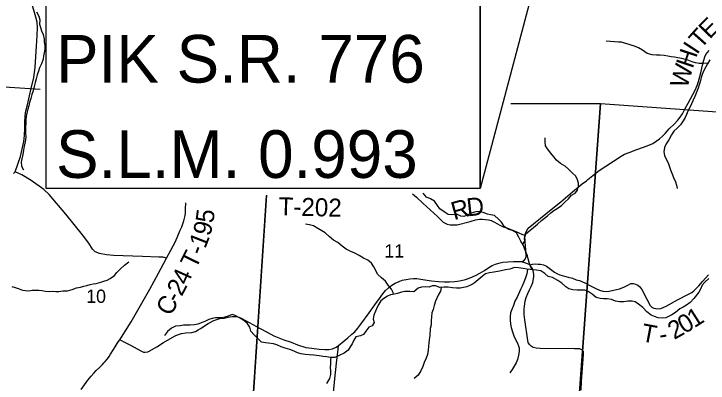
# Model space of a CAD drawing. Extents: x 0 to 40.8, y 0 to 22.
# Drawn here: x 5.517 to 7.699, y 15.059 to 16.222 of the extents above; entities that cross this region are included whole.
import ezdxf

# ---------------------------------------------------------------- set-up
doc = ezdxf.new("R2010")
doc.units = 0
for name, color, linetype in [('Default', 7, 'Continuous'), ('GM_X_County_Road', 7, 'Continuous'), ('GM_X_County_Road_Text', 7, 'Continuous'), ('GM_X_Minor_River', 7, 'Continuous'), ('GM_X_Section', 7, 'Continuous'), ('GM_X_Section_Text', 7, 'Continuous'), ('GM_X_Township_Road', 7, 'Continuous'), ('GM_X_Township_Road_Text', 7, 'Continuous')]:
    doc.layers.add(name, color=color, linetype=linetype)

msp = doc.modelspace()

# ---------------------------------------------------------------- linework, layer by layer
at = {"layer": 'Default'}
for points in [[(6.9829, 16.5037), (7.4797, 17.5479), (6.9829, 15.6724)], [(5.6188, 16.5037), (6.9829, 16.5037), (6.9829, 15.6724), (5.6188, 15.6724)]]:
    msp.add_lwpolyline(points, close=True, dxfattribs=at)
at = {"layer": 'GM_X_County_Road'}
for points in [[(5.5205, 15.725), (5.5376, 15.7735), (5.5479, 15.8205), (5.55, 15.8396), (5.5512, 15.8618), (5.551, 15.8837), (5.5538, 15.9116), (5.5595, 15.9361), (5.5656, 15.964), (5.5716, 15.9872), (5.5793, 16.0216), (5.5835, 16.0533), (5.5862, 16.0879), (5.5883, 16.1208), (5.5905, 16.1541), (5.5913, 16.1789), (5.5897, 16.1957), (5.5855, 16.2123), (5.5718, 16.2585)], [(7.3217, 15.7004), (7.3369, 15.7133), (7.3565, 15.7285), (7.3779, 15.7425), (7.4262, 15.7738), (7.4371, 15.7802), (7.4516, 15.786), (7.475, 15.7947), (7.4966, 15.802), (7.5132, 15.8086), (7.5256, 15.8142), (7.5358, 15.8211), (7.5467, 15.8292), (7.5559, 15.8374), (7.5646, 15.846), (7.5775, 15.8603), (7.5923, 15.875), (7.604, 15.8875), (7.6111, 15.8966), (7.6185, 15.9078), (7.6271, 15.9239), (7.6368, 15.9406), (7.6584, 15.9821), (7.6655, 15.9963), (7.6696, 16.0096), (7.6762, 16.0368), (7.6818, 16.0602), (7.6859, 16.0764), (7.6887, 16.0866), (7.6925, 16.0945), (7.7029, 16.1067)], [(5.5156, 15.7199), (5.5205, 15.725)], [(5.9972, 15.453), (5.9861, 15.4557), (5.9721, 15.4562), (5.9217, 15.4586), (5.83, 15.4613), (5.8081, 15.4634), (5.7861, 15.4673), (5.7729, 15.4727), (5.7643, 15.4815), (5.7523, 15.5005), (5.7331, 15.5261), (5.6798, 15.5916), (5.6283, 15.6533), (5.6112, 15.6694), (5.5708, 15.697), (5.5419, 15.7151), (5.5205, 15.725)], [(5.7287, 15.0393), (5.7498, 15.0691), (5.7597, 15.0811), (5.7681, 15.091), (5.7757, 15.0994), (5.7856, 15.1083), (5.7953, 15.1177), (5.7999, 15.1233), (5.804, 15.1279), (5.8111, 15.1365), (5.8162, 15.1434), (5.821, 15.151), (5.8299, 15.165), (5.835, 15.1734), (5.8413, 15.1838), (5.8462, 15.1907), (5.8497, 15.1955), (5.8548, 15.1935), (5.8627, 15.1899), (5.8815, 15.1802), (5.8953, 15.1726), (5.9161, 15.1607), (5.9245, 15.1574), (5.9301, 15.1571), (5.9375, 15.1584), (5.9423, 15.1604), (5.9665, 15.1741), (5.9876, 15.1871), (6.0145, 15.2031), (6.0242, 15.2085), (6.0318, 15.2118), (6.0443, 15.2159), (6.058, 15.2179), (6.0763, 15.2192), (6.088, 15.2225), (6.0967, 15.227), (6.1041, 15.2311), (6.1272, 15.2476), (6.146, 15.2565), (6.1648, 15.2629), (6.1781, 15.2639), (6.191, 15.2675), (6.203, 15.2693), (6.2093, 15.2693), (6.217, 15.269), (6.2246, 15.2672), (6.231, 15.2642), (6.2567, 15.2499), (6.291, 15.2311), (6.3129, 15.2197), (6.3342, 15.2085), (6.3658, 15.196), (6.3889, 15.1884), (6.409, 15.1805), (6.4349, 15.1721), (6.454, 15.1693), (6.4766, 15.1668), (6.495, 15.1655), (6.5074, 15.1655), (6.5184, 15.168), (6.5296, 15.1724), (6.5377, 15.178), (6.5554, 15.1922), (6.5673, 15.2018), (6.579, 15.2133), (6.5887, 15.2214), (6.5979, 15.2323), (6.6078, 15.2451), (6.634, 15.2809), (6.652, 15.3061), (6.666, 15.3262), (6.6764, 15.3404), (6.6853, 15.3516), (6.6942, 15.36), (6.7052, 15.3684), (6.7151, 15.3745), (6.7281, 15.3799), (6.738, 15.3832), (6.7499, 15.3862), (6.7616, 15.388), (6.7731, 15.3885), (6.784, 15.3885), (6.796, 15.3872), (6.8084, 15.3852), (6.8301, 15.3819), (6.8522, 15.3796), (6.8705, 15.3786), (6.8868, 15.3788), (6.9031, 15.3799), (6.912, 15.3809), (6.9229, 15.3824), (6.9369, 15.3862), (6.9519, 15.391), (6.9679, 15.3987), (6.9819, 15.4053), (6.9964, 15.4142), (7.0101, 15.4231), (7.0208, 15.4294), (7.031, 15.4343), (7.0417, 15.4376), (7.0544, 15.4399), (7.0701, 15.4414), (7.0879, 15.4427), (7.1115, 15.4421), (7.1201, 15.4447), (7.1247, 15.4496), (7.1275, 15.457), (7.1262, 15.4781), (7.1239, 15.5045), (7.1234, 15.5249), (7.1263, 15.534), (7.1337, 15.5472), (7.2062, 15.6063), (7.2362, 15.6306), (7.2726, 15.6614), (7.3031, 15.6873), (7.3171, 15.6965), (7.3217, 15.7004)], [(5.8497, 15.1955), (5.8857, 15.2529), (5.9441, 15.3555), (5.9718, 15.4058), (5.9972, 15.453)]]:
    msp.add_lwpolyline(points, dxfattribs=at)
at = {"layer": 'GM_X_Minor_River'}
for points in [[(5.5877, 16.2286), (5.5957, 16.2145), (5.5983, 16.2031), (5.5972, 16.1902), (5.6002, 16.1792), (5.6036, 16.169), (5.6093, 16.1576), (5.6116, 16.1428), (5.6123, 16.1333), (5.6139, 16.1227), (5.6139, 16.1113), (5.6116, 16.0996), (5.6097, 16.0897), (5.6089, 16.0795), (5.604, 16.0647), (5.5976, 16.0522), (5.5945, 16.0415), (5.5904, 16.0305), (5.5869, 16.0176), (5.5835, 16.0063), (5.5809, 15.993), (5.5775, 15.9797), (5.5737, 15.9687), (5.5699, 15.9562), (5.5665, 15.9433), (5.5642, 15.9331), (5.5612, 15.9224), (5.5578, 15.9099), (5.5555, 15.8989), (5.5543, 15.8894), (5.554, 15.8773), (5.5532, 15.8678), (5.5536, 15.8568), (5.5532, 15.8469), (5.554, 15.834), (5.5521, 15.8192), (5.5494, 15.8056), (5.5475, 15.7935), (5.5445, 15.779), (5.5422, 15.7661), (5.5403, 15.7555), (5.5411, 15.743), (5.5475, 15.7316)], [(7.6986, 16.0667), (7.6847, 16.0664), (7.6718, 16.066), (7.6597, 16.0675), (7.6491, 16.0709), (7.6385, 16.0755), (7.6279, 16.0789), (7.6169, 16.0816), (7.6044, 16.0842), (7.5942, 16.0861), (7.5836, 16.0873), (7.573, 16.0892), (7.5608, 16.0914), (7.5476, 16.0922), (7.537, 16.0926), (7.5233, 16.0937), (7.5078, 16.0979), (7.4934, 16.1081), (7.4805, 16.1157), (7.468, 16.1206), (7.4578, 16.1241), (7.4479, 16.1267), (7.437, 16.1301), (7.4275, 16.1328), (7.4176, 16.1328), (7.4048, 16.1339), (7.3911, 16.1351), (7.379, 16.1362)], [(7.7044, 16.077), (7.6976, 16.0649), (7.6923, 16.0554), (7.6851, 16.0417), (7.6805, 16.0311), (7.6775, 16.0216), (7.6749, 16.0083), (7.6718, 15.9989), (7.6684, 15.9882), (7.662, 15.9723), (7.6578, 15.9621), (7.6517, 15.9488), (7.6476, 15.9393), (7.6434, 15.9294), (7.6362, 15.9158), (7.6317, 15.9055), (7.6271, 15.8961), (7.6207, 15.8858), (7.6123, 15.8729), (7.6017, 15.8627), (7.5915, 15.8524), (7.5843, 15.8414), (7.5756, 15.8251), (7.5676, 15.8126), (7.5627, 15.8012), (7.56, 15.7879), (7.5619, 15.7762), (7.5668, 15.7663), (7.5737, 15.7534), (7.5771, 15.7436), (7.5816, 15.7314), (7.5858, 15.7204), (7.5907, 15.7071), (7.5968, 15.6931), (7.6002, 15.6832), (7.6024, 15.6719)], [(7.1165, 15.4974), (7.1237, 15.5068), (7.1226, 15.5163), (7.126, 15.5296), (7.1401, 15.5413), (7.1503, 15.5497), (7.1629, 15.5599), (7.1754, 15.5713), (7.1852, 15.5784), (7.1947, 15.586), (7.205, 15.5959), (7.2148, 15.6031), (7.2247, 15.6091), (7.2383, 15.6186), (7.2493, 15.6292), (7.2604, 15.6394), (7.2698, 15.6512), (7.2812, 15.6576), (7.2892, 15.6671), (7.2915, 15.6792), (7.2915, 15.6891), (7.2877, 15.7023), (7.2828, 15.7118), (7.2726, 15.7206), (7.2605, 15.7327), (7.2499, 15.7422), (7.2355, 15.7506), (7.2223, 15.7616), (7.2147, 15.7719), (7.2045, 15.7833), (7.1943, 15.797), (7.1887, 15.8065), (7.1868, 15.8205), (7.1876, 15.8315)], [(7.1466, 15.4167), (7.141, 15.4271), (7.1369, 15.4393), (7.1342, 15.4507), (7.132, 15.4602), (7.1263, 15.4731), (7.1226, 15.4829), (7.1195, 15.4924), (7.1112, 15.5061), (7.1041, 15.519), (7.0969, 15.5323), (7.0848, 15.5399), (7.073, 15.5433), (7.0598, 15.5521), (7.05, 15.5658), (7.0409, 15.5753), (7.0284, 15.5874), (7.0155, 15.5893), (7.0057, 15.592), (6.9921, 15.597), (6.9792, 15.5996), (6.9689, 15.5989), (6.9545, 15.5944), (6.942, 15.5879), (6.9314, 15.5842), (6.9216, 15.5857), (6.9095, 15.591), (6.8939, 15.5895), (6.8826, 15.5907), (6.8693, 15.5987), (6.8564, 15.6086), (6.8485, 15.6184), (6.8394, 15.6321), (6.8269, 15.6397), (6.8137, 15.6451), (6.8039, 15.6576)], [(6.7103, 15.3389), (6.709, 15.3451), (6.7037, 15.3554), (6.6939, 15.3683), (6.6848, 15.3808), (6.6723, 15.3907), (6.6602, 15.4021), (6.6549, 15.4143), (6.6485, 15.4257), (6.6413, 15.4367), (6.6292, 15.4462), (6.6164, 15.4534), (6.6024, 15.4618), (6.5884, 15.4682), (6.5762, 15.4736), (6.5615, 15.4816), (6.5486, 15.4911), (6.535, 15.5021), (6.5221, 15.5097), (6.5077, 15.5207), (6.4956, 15.5329), (6.4854, 15.5394), (6.4726, 15.5462), (6.4593, 15.5546), (6.4461, 15.558), (6.4339, 15.5603)], [(5.5107, 15.3636), (5.5205, 15.3606), (5.5338, 15.356), (5.5437, 15.3526), (5.5535, 15.3507), (5.5634, 15.3503), (5.5743, 15.3519), (5.5849, 15.3522), (5.5952, 15.3522), (5.6054, 15.3511), (5.6149, 15.3492), (5.6297, 15.3484), (5.6391, 15.3488), (5.6486, 15.348), (5.6584, 15.3484), (5.6713, 15.3496), (5.6857, 15.3503), (5.6997, 15.3545), (5.7134, 15.3594), (5.7266, 15.3613), (5.7373, 15.3643), (5.7467, 15.3666), (5.7562, 15.3697), (5.7657, 15.3719), (5.7751, 15.3734), (5.7899, 15.3772), (5.8001, 15.3807), (5.81, 15.3833), (5.8195, 15.3886), (5.8327, 15.3989), (5.8407, 15.4083), (5.8517, 15.4197), (5.8642, 15.4307), (5.8778, 15.441)], [(7.1035, 15.4223), (7.0906, 15.4238), (7.0762, 15.4185), (7.0622, 15.4159), (7.0486, 15.4136), (7.0387, 15.4114), (7.0254, 15.4087), (7.0122, 15.4072), (7.0001, 15.4038), (6.9887, 15.3951), (6.9769, 15.3845), (6.9644, 15.3743), (6.9542, 15.369), (6.9405, 15.3626), (6.9303, 15.3603), (6.9204, 15.3588), (6.9083, 15.3581), (6.8954, 15.3596), (6.8825, 15.3615), (6.8681, 15.3616), (6.856, 15.3608), (6.842, 15.3654), (6.8322, 15.3654), (6.8227, 15.3616), (6.8106, 15.3624), (6.7988, 15.3617), (6.7882, 15.3583), (6.7742, 15.3473), (6.7613, 15.3477), (6.7461, 15.3485), (6.7351, 15.3455), (6.723, 15.3413), (6.7135, 15.3394), (6.701, 15.3375), (6.6912, 15.3334), (6.6802, 15.3262), (6.6703, 15.3182), (6.6642, 15.3084), (6.6593, 15.2989), (6.654, 15.2864), (6.649, 15.2739), (6.646, 15.2614), (6.6497, 15.2507), (6.6433, 15.2401), (6.6323, 15.236), (6.6232, 15.2227), (6.6163, 15.2128), (6.6061, 15.2083), (6.5924, 15.2053), (6.5852, 15.1943), (6.5799, 15.1837), (6.5742, 15.1735), (6.5674, 15.1636), (6.5552, 15.1541), (6.5416, 15.1473), (6.526, 15.1405), (6.5113, 15.1402), (6.501, 15.1425), (6.4897, 15.1436), (6.4764, 15.1452), (6.4601, 15.1475), (6.4457, 15.1486), (6.4329, 15.1498), (6.4204, 15.1517), (6.409, 15.1544), (6.398, 15.1605), (6.3848, 15.1658), (6.37, 15.17), (6.3571, 15.1734), (6.3431, 15.1799), (6.3329, 15.183), (6.3177, 15.1849), (6.3075, 15.186), (6.2958, 15.1883), (6.284, 15.1997), (6.2727, 15.2111), (6.2617, 15.2233), (6.2583, 15.2354), (6.2504, 15.248), (6.2368, 15.259), (6.2258, 15.2647), (6.2126, 15.2723), (6.2027, 15.2761), (6.191, 15.2708), (6.1804, 15.2667), (6.1705, 15.2648), (6.1603, 15.2648), (6.1504, 15.2656), (6.1402, 15.2633), (6.1303, 15.2599), (6.1193, 15.2547), (6.1091, 15.2505), (6.0951, 15.2456), (6.0845, 15.2426), (6.0712, 15.2418), (6.0614, 15.2422), (6.0504, 15.2415), (6.0398, 15.2404), (6.0246, 15.2389), (6.0128, 15.2328), (5.9999, 15.2222)], [(7.1318, 15.4182), (7.1292, 15.4032), (7.1251, 15.3907), (7.1201, 15.3775), (7.1148, 15.3646), (7.1095, 15.3543), (7.0988, 15.3304), (7.092, 15.3176), (7.0874, 15.3043), (7.0828, 15.2914), (7.0783, 15.2808), (7.0767, 15.2694), (7.0767, 15.2588), (7.0782, 15.2455), (7.0808, 15.2349), (7.085, 15.2208), (7.0884, 15.2079), (7.0948, 15.195), (7.1005, 15.1851), (7.105, 15.1707), (7.1053, 15.1593), (7.103, 15.1472), (7.1, 15.1335), (7.0962, 15.1233), (7.0897, 15.1127), (7.0836, 15.1028), (7.0757, 15.0922)], [(7.702, 15.3894), (7.6895, 15.3773), (7.6812, 15.3675), (7.6758, 15.3553), (7.6705, 15.3455), (7.6546, 15.3258), (7.6428, 15.3133), (7.6311, 15.3053), (7.6212, 15.2989), (7.611, 15.2932), (7.5973, 15.2822), (7.5859, 15.275), (7.567, 15.2652), (7.556, 15.2637), (7.5423, 15.2652), (7.5306, 15.2691), (7.52, 15.274), (7.5071, 15.2843), (7.4939, 15.2972), (7.481, 15.3082), (7.4704, 15.3151), (7.4606, 15.3173), (7.447, 15.3174), (7.4341, 15.3155), (7.4204, 15.3151), (7.4087, 15.3171), (7.3958, 15.3228), (7.3826, 15.3251), (7.3704, 15.3247), (7.3606, 15.3259), (7.3473, 15.3289), (7.3345, 15.3396), (7.322, 15.3479), (7.3121, 15.3517), (7.3012, 15.3525), (7.2883, 15.3522), (7.2746, 15.3533), (7.2621, 15.356), (7.2523, 15.3632), (7.2398, 15.3739), (7.2266, 15.3826), (7.2103, 15.3925), (7.197, 15.3955), (7.1857, 15.4043), (7.1732, 15.4127), (7.16, 15.4157), (7.1493, 15.4165), (7.1399, 15.4173), (7.13, 15.4184), (7.1175, 15.4203), (7.1035, 15.4223)], [(6.86, 15.3611), (6.8579, 15.3494), (6.8507, 15.3365), (6.8461, 15.3271), (6.8419, 15.3176), (6.8377, 15.3035), (6.8347, 15.291), (6.8313, 15.2808), (6.8297, 15.2683), (6.8293, 15.2558), (6.8285, 15.2432), (6.8259, 15.2311), (6.8243, 15.2091), (6.8228, 15.1962), (6.8216, 15.1867), (6.8205, 15.1761), (6.8197, 15.1636), (6.817, 15.1499), (6.8132, 15.1385), (6.8071, 15.1245), (6.8029, 15.1116), (6.7961, 15.0987), (6.7874, 15.0851), (6.7752, 15.0745)], [(5.9999, 15.2222), (5.9901, 15.2093)], [(6.5132, 15.1402), (6.5124, 15.133), (6.512, 15.1197), (6.5116, 15.1102), (6.5127, 15.0965), (6.5127, 15.0867), (6.5093, 15.0742), (6.5001, 15.0582)]]:
    msp.add_lwpolyline(points, dxfattribs=at)
at = {"layer": 'GM_X_Section'}
for points in [[(6.3112, 15.6512), (6.2633, 14.9194), (5.2555, 14.9926), (5.3264, 16.0026), (5.5999, 15.9856)], [(7.079, 15.9397), (7.3612, 15.9396), (7.2868, 14.9136), (6.2633, 14.9194), (6.311, 15.6491)]]:
    msp.add_lwpolyline(points, dxfattribs=at)
msp.add_lwpolyline([(8.344, 15.8695), (8.2661, 14.9102), (8.2617, 14.8595), (7.7715, 14.8766), (7.2868, 14.9136), (7.3612, 15.9396)], close=True, dxfattribs=at)
at = {"layer": 'GM_X_Township_Road'}
for points in [[(6.7703, 15.6556), (6.7831, 15.6446), (6.8027, 15.6266), (6.8485, 15.5846), (6.8546, 15.5778), (6.8622, 15.5704), (6.867, 15.5661), (6.8726, 15.5628), (6.8792, 15.5602), (6.8881, 15.5584), (6.8986, 15.5574), (6.91, 15.5582), (6.951, 15.5689), (6.9685, 15.5732), (6.981, 15.5755), (6.9899, 15.5755), (6.9995, 15.575), (7.0092, 15.5734), (7.0179, 15.5711), (7.0257, 15.5676), (7.0377, 15.5612), (7.0451, 15.5566), (7.0552, 15.5521), (7.0664, 15.548), (7.0771, 15.5442), (7.0926, 15.5381), (7.1046, 15.5332), (7.1163, 15.5274), (7.1234, 15.5249)], [(5.9972, 15.453), (6.0105, 15.4785), (6.0245, 15.5055), (6.04, 15.5409), (6.0448, 15.5518), (6.0512, 15.5701), (6.0555, 15.5869), (6.0562, 15.5943), (6.0565, 15.6073), (6.0576, 15.6269)], [(7.1115, 15.4421), (7.1224, 15.4389), (7.1303, 15.4364), (7.1359, 15.4336), (7.1397, 15.4318), (7.1476, 15.4336), (7.1567, 15.4346), (7.1649, 15.4343), (7.172, 15.4338), (7.1819, 15.432), (7.1918, 15.4282), (7.2167, 15.4094), (7.2236, 15.4046), (7.2333, 15.4005), (7.2483, 15.3967), (7.2595, 15.3934), (7.2727, 15.3896), (7.2849, 15.3852), (7.2953, 15.3824), (7.3121, 15.3748), (7.3258, 15.3682), (7.3467, 15.3575), (7.3576, 15.3524), (7.3681, 15.3491), (7.3787, 15.3481), (7.3889, 15.3489), (7.4212, 15.3565), (7.4347, 15.3616), (7.4489, 15.3692), (7.4566, 15.373), (7.4637, 15.3735), (7.4716, 15.3712), (7.4782, 15.3679), (7.4845, 15.3629), (7.4909, 15.3547), (7.5064, 15.3242), (7.5171, 15.3036), (7.5222, 15.2983), (7.5288, 15.2952), (7.5349, 15.2942), (7.5418, 15.2939), (7.5512, 15.2949), (7.5677, 15.3016), (7.6036, 15.3214), (7.6379, 15.3395), (7.6478, 15.345), (7.6544, 15.3504), (7.6699, 15.3654), (7.6832, 15.3801), (7.7012, 15.4002)], [(7.3003, 15.037), (7.3013, 15.0642), (7.3079, 15.1492), (7.3082, 15.1543), (7.3072, 15.1596), (7.3023, 15.1644), (7.296, 15.167), (7.2891, 15.1675), (7.2795, 15.168), (7.1711, 15.1688), (7.1592, 15.1693), (7.1495, 15.1721), (7.1429, 15.1756), (7.1375, 15.1807), (7.1342, 15.1871), (7.133, 15.1934), (7.123, 15.2588), (7.121, 15.2758), (7.1213, 15.2934), (7.1225, 15.3023), (7.1241, 15.3175), (7.1274, 15.329), (7.1327, 15.342), (7.1383, 15.3537), (7.1431, 15.3641), (7.148, 15.3765), (7.1508, 15.3875), (7.1518, 15.3956), (7.1513, 15.403), (7.1492, 15.4129), (7.1469, 15.4203), (7.1436, 15.4261), (7.1397, 15.4318)], [(6.4841, 14.9319), (6.4894, 14.9455), (6.495, 14.9605), (6.5013, 14.9753), (6.5064, 14.9864), (6.5105, 14.9966), (6.5173, 15.0119), (6.5217, 15.0297), (6.5255, 15.0727), (6.5308, 15.122), (6.5364, 15.1668), (6.5377, 15.178)]]:
    msp.add_lwpolyline(points, dxfattribs=at)

# ---------------------------------------------------------------- texts
at = {"layer": 'Default'}
for s, p in [('PIK S.R. 776', (5.6493, 16.0057)), ('S.L.M. 0.993', (5.6493, 15.7057))]:
    msp.add_text(s, height=0.15, dxfattribs=at).set_placement(p)
at = {"layer": 'GM_X_County_Road_Text'}
for s, rotation, p in [('E', 45.6061, (7.7043, 16.1407)), ('T', 48.2017, (7.6765, 16.1095)), ('I', 56.7559, (7.665, 16.0917)), ('H', 71.6411, (7.651, 16.0478)), ('W', 74.4209, (7.6335, 15.9851)), ('4', 65.7784, (6.0627, 15.3648)), ('2', 62.0796, (6.0445, 15.3303)), ('C', 60.3597, (6.0091, 15.2677)), ('-', 60.7459, (6.0324, 15.3086))]:
    msp.add_text(s, height=0.0568, rotation=rotation, dxfattribs=at).set_placement(p)
at = {"layer": 'GM_X_Section_Text'}
for s, p in [('11', (6.6817, 15.455)), ('10', (5.7442, 15.3121))]:
    msp.add_text(s, height=0.04186, rotation=0, dxfattribs=at).set_placement(p)
at = {"layer": 'GM_X_Township_Road_Text'}
for s, height, rotation, p in [('T-202', 0.05682, 358.5957, (6.3485, 15.588)), ('R', 0.0568, 15.5964, (6.9006, 15.5723)), ('D', 0.0568, 6.2855, (6.9432, 15.5843)), ('5', 0.0568, 82.4645, (6.1439, 15.5616)), ('9', 0.0568, 75.2416, (6.1335, 15.5201)), ('1', 0.0568, 68.4885, (6.1183, 15.4806)), ('T', 0.0568, 63.5346, (6.0885, 15.416)), ('-', 0.0568, 68.0475, (6.1094, 15.4585)), ('0', 0.0568, 31.0992, (7.6249, 15.2132)), ('1', 0.0568, 32.4263, (7.656, 15.232)), ('2', 0.0568, 29.51, (7.5929, 15.1951)), ('T', 0.0568, 349.3843, (7.4862, 15.1919)), ('-', 0.0568, 9.957, (7.5501, 15.1839))]:
    msp.add_text(s, height=height, rotation=rotation, dxfattribs=at).set_placement(p)

doc.saveas('drawing.dxf')
